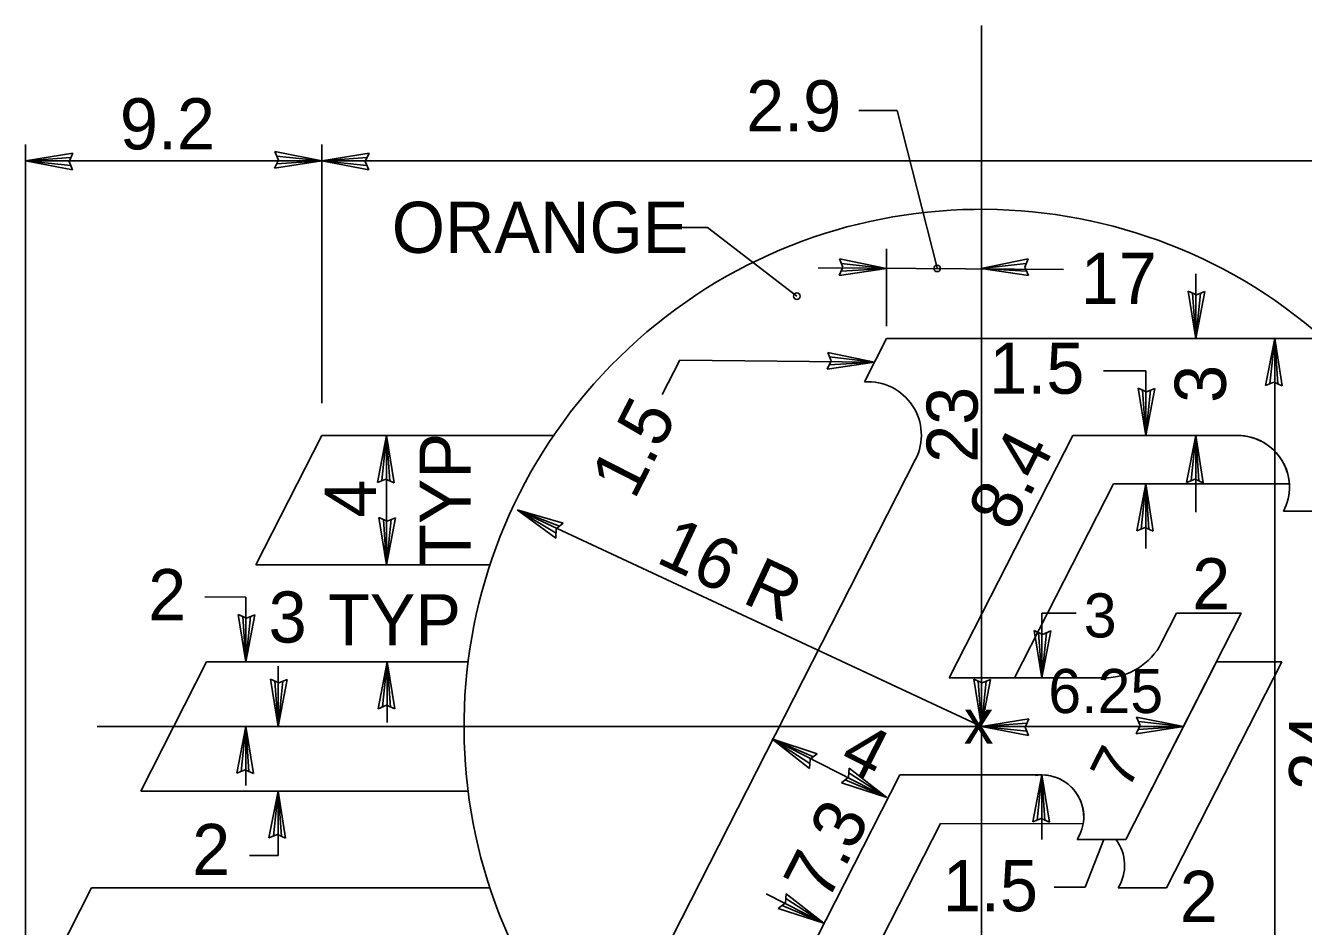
# Model space of a CAD drawing. Extents: x 10268197 to 10269179, y 2141503 to 2142677.
# Drawn here: x 10268467.88 to 10268485.36, y 2142125.76 to 2142138.09 of the extents above; entities that cross this region are included whole.
import ezdxf

# ---------------------------------------------------------------- set-up
doc = ezdxf.new("R2010")
doc.units = 0
for name, color, linetype in [('1', 7, 'Continuous'), ('52', 7, 'Continuous'), ('SOILS_SP83_SHP', 7, 'Continuous')]:
    doc.layers.add(name, color=color, linetype=linetype)

msp = doc.modelspace()

# ---------------------------------------------------------------- linework, layer by layer
at = {"layer": '1'}
for p, q in [((10268480.958, 2142117.747), (10268480.958, 2142138.09)), ((10268479.802, 2142136.926), (10268479.281, 2142136.929)), ((10268479.802, 2142136.926), (10268480.353, 2142134.772)), ((10268467.878, 2142125.164), (10268467.878, 2142136.461)), ((10268471.932, 2142132.921), (10268471.932, 2142136.461)), ((10268467.878, 2142136.24), (10268491.08, 2142136.24)), ((10268476.41, 2142135.328), (10268477.21, 2142135.328)), ((10268477.21, 2142135.328), (10268478.431, 2142134.386)), ((10268479.658, 2142133.976), (10268479.658, 2142135.032)), ((10268482.078, 2142134.75), (10268478.725, 2142134.774)), ((10268483.89, 2142134.691), (10268483.89, 2142133.806)), ((10268484.969, 2142123.188), (10268484.969, 2142133.806)), ((10268476.59, 2142133.039), (10268476.829, 2142133.508)), ((10268476.829, 2142133.508), (10268479.495, 2142133.484)), ((10268483.206, 2142133.364), (10268482.628, 2142133.364)), ((10268483.206, 2142133.364), (10268483.206, 2142132.479)), ((10268472.817, 2142130.709), (10268472.817, 2142132.479)), ((10268480.517, 2142129.161), (10268482.207, 2142132.479)), ((10268482.207, 2142132.479), (10268484.462, 2142132.479)), ((10268483.89, 2142132.479), (10268483.89, 2142131.427)), ((10268482.763, 2142131.815), (10268481.411, 2142129.161)), ((10268485.17, 2142131.815), (10268482.763, 2142131.815)), ((10268483.206, 2142131.815), (10268483.206, 2142130.93)), ((10268480.958, 2142128.497), (10268474.605, 2142131.459)), ((10268470.892, 2142130.267), (10268470.332, 2142130.27)), ((10268470.892, 2142129.382), (10268470.892, 2142130.267)), ((10268481.783, 2142130.046), (10268481.783, 2142129.161)), ((10268481.783, 2142130.046), (10268482.252, 2142130.046)), ((10268471.334, 2142128.497), (10268471.334, 2142129.322)), ((10268472.827, 2142128.552), (10268472.827, 2142129.382)), ((10268482.934, 2142126.949), (10268484.174, 2142129.382)), ((10268485.067, 2142129.382), (10268483.489, 2142126.285)), ((10268484.174, 2142129.382), (10268485.067, 2142129.382)), ((10268481.411, 2142129.161), (10268480.517, 2142129.161)), ((10268468.86, 2142128.497), (10268483.723, 2142128.497)), ((10268470.892, 2142127.689), (10268470.892, 2142128.497)), ((10268479.664, 2142127.521), (10268478.087, 2142128.325)), ((10268478.376, 2142124.957), (10268479.841, 2142127.834)), ((10268479.841, 2142127.834), (10268481.699, 2142127.827)), ((10268481.783, 2142127.834), (10268481.783, 2142126.949)), ((10268471.334, 2142126.727), (10268471.334, 2142127.612)), ((10268480.396, 2142127.168), (10268479.269, 2142124.957)), ((10268482.349, 2142127.162), (10268480.396, 2142127.168)), ((10268482.375, 2142126.297), (10268482.631, 2142126.949)), ((10268482.795, 2142126.949), (10268482.934, 2142126.949)), ((10268471.334, 2142126.727), (10268470.943, 2142126.731)), ((10268478.8, 2142125.802), (10268478.012, 2142126.204)), ((10268481.95, 2142126.297), (10268482.375, 2142126.297)), ((10268483.489, 2142126.285), (10268482.826, 2142126.285))]:
    msp.add_line(p, q, dxfattribs=at)
for centre in [(10268480.35, 2142134.766), (10268478.431, 2142134.385)]:
    msp.add_circle(centre, 0.0442, dxfattribs=at)
for centre, radius, start, end in [((10268484.463, 2142131.77), 0.708, 3.5833, 90), ((10268481.782, 2142127.257), 0.575, 350.3502, 98.3344), ((10268482.341, 2142126.594), 0.575, 327.421, 37.9799)]:
    msp.add_arc(centre, radius, start, end, dxfattribs=at)
at = {"layer": '52'}
for p, q in [((10268467.878, 2142136.24), (10268468.525, 2142136.342)), ((10268468.474, 2142136.229), (10268468.525, 2142136.342)), ((10268471.932, 2142136.24), (10268471.289, 2142136.364)), ((10268471.289, 2142136.364), (10268471.337, 2142136.249)), ((10268471.932, 2142136.24), (10268471.314, 2142136.304)), ((10268471.932, 2142136.24), (10268472.579, 2142136.342)), ((10268472.527, 2142136.229), (10268472.579, 2142136.342)), ((10268467.878, 2142136.24), (10268468.498, 2142136.283)), ((10268467.878, 2142136.24), (10268468.521, 2142136.114)), ((10268467.878, 2142136.24), (10268468.496, 2142136.174)), ((10268468.521, 2142136.114), (10268468.474, 2142136.229)), ((10268471.337, 2142136.249), (10268471.285, 2142136.137)), ((10268471.932, 2142136.24), (10268471.285, 2142136.137)), ((10268471.932, 2142136.24), (10268471.313, 2142136.196)), ((10268471.932, 2142136.24), (10268472.552, 2142136.283)), ((10268471.932, 2142136.24), (10268472.575, 2142136.114)), ((10268471.932, 2142136.24), (10268472.55, 2142136.174)), ((10268472.575, 2142136.114), (10268472.527, 2142136.229)), ((10268479.657, 2142134.765), (10268479.015, 2142134.896)), ((10268479.015, 2142134.896), (10268479.061, 2142134.781)), ((10268480.954, 2142134.765), (10268481.596, 2142134.896)), ((10268481.596, 2142134.896), (10268481.55, 2142134.781)), ((10268479.061, 2142134.781), (10268479.009, 2142134.668)), ((10268479.657, 2142134.765), (10268479.009, 2142134.668)), ((10268479.657, 2142134.765), (10268479.037, 2142134.727)), ((10268479.657, 2142134.765), (10268479.039, 2142134.835)), ((10268480.954, 2142134.765), (10268481.571, 2142134.835)), ((10268480.954, 2142134.765), (10268481.602, 2142134.668)), ((10268480.954, 2142134.765), (10268481.574, 2142134.727)), ((10268481.55, 2142134.781), (10268481.602, 2142134.668)), ((10268483.89, 2142133.806), (10268483.787, 2142134.453)), ((10268483.899, 2142134.402), (10268483.787, 2142134.453)), ((10268483.89, 2142133.806), (10268483.846, 2142134.425)), ((10268483.89, 2142133.806), (10268484.014, 2142134.449)), ((10268483.89, 2142133.806), (10268483.954, 2142134.424)), ((10268484.014, 2142134.449), (10268483.899, 2142134.402)), ((10268484.969, 2142133.806), (10268484.844, 2142133.163)), ((10268484.969, 2142133.806), (10268484.904, 2142133.188)), ((10268484.969, 2142133.806), (10268485.072, 2142133.159)), ((10268484.969, 2142133.806), (10268485.012, 2142133.187)), ((10268478.899, 2142133.5), (10268478.847, 2142133.387)), ((10268479.495, 2142133.484), (10268478.853, 2142133.615)), ((10268478.853, 2142133.615), (10268478.899, 2142133.5)), ((10268479.495, 2142133.484), (10268478.878, 2142133.554)), ((10268479.495, 2142133.484), (10268478.847, 2142133.387)), ((10268479.495, 2142133.484), (10268478.875, 2142133.446)), ((10268484.844, 2142133.163), (10268484.958, 2142133.21)), ((10268484.958, 2142133.21), (10268485.072, 2142133.159)), ((10268483.206, 2142132.479), (10268483.103, 2142133.126)), ((10268483.215, 2142133.074), (10268483.103, 2142133.126)), ((10268483.206, 2142132.479), (10268483.162, 2142133.098)), ((10268483.206, 2142132.479), (10268483.33, 2142133.121)), ((10268483.206, 2142132.479), (10268483.27, 2142133.097)), ((10268483.33, 2142133.121), (10268483.215, 2142133.074)), ((10268472.817, 2142132.479), (10268472.692, 2142131.836)), ((10268472.817, 2142132.479), (10268472.752, 2142131.861)), ((10268472.817, 2142132.479), (10268472.92, 2142131.832)), ((10268472.817, 2142132.479), (10268472.861, 2142131.859)), ((10268483.89, 2142132.479), (10268483.764, 2142131.836)), ((10268483.89, 2142132.479), (10268483.825, 2142131.861)), ((10268483.89, 2142132.479), (10268483.992, 2142131.832)), ((10268483.89, 2142132.479), (10268483.933, 2142131.859)), ((10268472.692, 2142131.836), (10268472.807, 2142131.883)), ((10268472.807, 2142131.883), (10268472.92, 2142131.832)), ((10268483.206, 2142131.815), (10268483.081, 2142131.173)), ((10268483.206, 2142131.815), (10268483.141, 2142131.197)), ((10268483.206, 2142131.815), (10268483.308, 2142131.168)), ((10268483.206, 2142131.815), (10268483.249, 2142131.196)), ((10268483.764, 2142131.836), (10268483.879, 2142131.883)), ((10268483.879, 2142131.883), (10268483.992, 2142131.832)), ((10268474.605, 2142131.459), (10268475.234, 2142131.279)), ((10268474.605, 2142131.459), (10268475.135, 2142131.075)), ((10268474.605, 2142131.459), (10268475.137, 2142131.14)), ((10268474.605, 2142131.459), (10268475.184, 2142131.237)), ((10268472.817, 2142130.709), (10268472.714, 2142131.356)), ((10268472.827, 2142131.305), (10268472.714, 2142131.356)), ((10268472.817, 2142130.709), (10268472.774, 2142131.328)), ((10268472.817, 2142130.709), (10268472.942, 2142131.352)), ((10268472.817, 2142130.709), (10268472.881, 2142131.327)), ((10268472.942, 2142131.352), (10268472.827, 2142131.305)), ((10268475.14, 2142131.199), (10268475.234, 2142131.279)), ((10268483.081, 2142131.173), (10268483.196, 2142131.219)), ((10268483.196, 2142131.219), (10268483.308, 2142131.168)), ((10268475.135, 2142131.075), (10268475.14, 2142131.199)), ((10268470.892, 2142129.382), (10268470.789, 2142130.029)), ((10268470.902, 2142129.977), (10268470.789, 2142130.029)), ((10268470.892, 2142129.382), (10268470.849, 2142130.001)), ((10268470.892, 2142129.382), (10268471.017, 2142130.024)), ((10268470.892, 2142129.382), (10268470.957, 2142130)), ((10268471.017, 2142130.024), (10268470.902, 2142129.977)), ((10268481.783, 2142129.161), (10268481.68, 2142129.808)), ((10268481.793, 2142129.756), (10268481.68, 2142129.808)), ((10268481.783, 2142129.161), (10268481.739, 2142129.78)), ((10268481.783, 2142129.161), (10268481.907, 2142129.803)), ((10268481.783, 2142129.161), (10268481.847, 2142129.779)), ((10268481.907, 2142129.803), (10268481.793, 2142129.756)), ((10268472.827, 2142129.382), (10268472.703, 2142128.739)), ((10268472.827, 2142129.382), (10268472.763, 2142128.764)), ((10268472.827, 2142129.382), (10268472.93, 2142128.735)), ((10268472.827, 2142129.382), (10268472.871, 2142128.762)), ((10268471.334, 2142128.497), (10268471.232, 2142129.144)), ((10268471.344, 2142129.092), (10268471.232, 2142129.144)), ((10268471.334, 2142128.497), (10268471.459, 2142129.14)), ((10268471.459, 2142129.14), (10268471.344, 2142129.092)), ((10268480.958, 2142128.497), (10268480.855, 2142129.144)), ((10268480.968, 2142129.092), (10268480.855, 2142129.144)), ((10268480.958, 2142128.497), (10268481.082, 2142129.14)), ((10268481.082, 2142129.14), (10268480.968, 2142129.092)), ((10268471.334, 2142128.497), (10268471.291, 2142129.116)), ((10268471.334, 2142128.497), (10268471.399, 2142129.115)), ((10268480.958, 2142128.497), (10268480.914, 2142129.116)), ((10268480.958, 2142128.497), (10268481.022, 2142129.115)), ((10268472.703, 2142128.739), (10268472.817, 2142128.786)), ((10268472.817, 2142128.786), (10268472.93, 2142128.735)), ((10268480.958, 2142128.497), (10268481.605, 2142128.599)), ((10268481.553, 2142128.487), (10268481.605, 2142128.599)), ((10268483.723, 2142128.497), (10268483.08, 2142128.622)), ((10268483.08, 2142128.622), (10268483.127, 2142128.507)), ((10268470.892, 2142128.497), (10268470.767, 2142127.854)), ((10268470.892, 2142128.497), (10268470.827, 2142127.879)), ((10268470.892, 2142128.497), (10268470.995, 2142127.85)), ((10268470.892, 2142128.497), (10268470.935, 2142127.877)), ((10268480.958, 2142128.497), (10268481.577, 2142128.54)), ((10268480.958, 2142128.497), (10268481.6, 2142128.372)), ((10268480.958, 2142128.497), (10268481.576, 2142128.432)), ((10268481.6, 2142128.372), (10268481.553, 2142128.487)), ((10268483.127, 2142128.507), (10268483.076, 2142128.394)), ((10268483.723, 2142128.497), (10268483.076, 2142128.394)), ((10268483.723, 2142128.497), (10268483.103, 2142128.453)), ((10268483.723, 2142128.497), (10268483.105, 2142128.562)), ((10268478.087, 2142128.325), (10268478.71, 2142128.123)), ((10268478.087, 2142128.325), (10268478.603, 2142127.922)), ((10268478.087, 2142128.325), (10268478.608, 2142127.987)), ((10268478.087, 2142128.325), (10268478.659, 2142128.082)), ((10268478.613, 2142128.046), (10268478.71, 2142128.123)), ((10268470.767, 2142127.854), (10268470.882, 2142127.901)), ((10268470.882, 2142127.901), (10268470.995, 2142127.85)), ((10268478.603, 2142127.922), (10268478.613, 2142128.046)), ((10268479.148, 2142127.925), (10268479.138, 2142127.801)), ((10268479.664, 2142127.521), (10268479.148, 2142127.925)), ((10268479.138, 2142127.801), (10268479.041, 2142127.723)), ((10268479.664, 2142127.521), (10268479.041, 2142127.723)), ((10268479.664, 2142127.521), (10268479.092, 2142127.764)), ((10268479.664, 2142127.521), (10268479.143, 2142127.86)), ((10268481.783, 2142127.834), (10268481.658, 2142127.191)), ((10268481.783, 2142127.834), (10268481.718, 2142127.215)), ((10268481.783, 2142127.834), (10268481.886, 2142127.186)), ((10268481.783, 2142127.834), (10268481.826, 2142127.214)), ((10268471.334, 2142127.612), (10268471.209, 2142126.969)), ((10268471.334, 2142127.612), (10268471.269, 2142126.994)), ((10268471.334, 2142127.612), (10268471.437, 2142126.965)), ((10268471.334, 2142127.612), (10268471.378, 2142126.993)), ((10268481.658, 2142127.191), (10268481.773, 2142127.237)), ((10268481.773, 2142127.237), (10268481.886, 2142127.186)), ((10268471.209, 2142126.969), (10268471.324, 2142127.016)), ((10268471.324, 2142127.016), (10268471.437, 2142126.965)), ((10268478.284, 2142126.206), (10268478.274, 2142126.082)), ((10268478.8, 2142125.802), (10268478.284, 2142126.206)), ((10268478.274, 2142126.082), (10268478.177, 2142126.005)), ((10268478.8, 2142125.802), (10268478.177, 2142126.005)), ((10268478.8, 2142125.802), (10268478.229, 2142126.045)), ((10268478.8, 2142125.802), (10268478.279, 2142126.14))]:
    msp.add_line(p, q, dxfattribs=at)
at = {"layer": 'SOILS_SP83_SHP'}
for p, q in [((10268479.357, 2142133.212), (10268479.658, 2142133.806)), ((10268479.658, 2142133.806), (10268487.18, 2142133.806)), ((10268471.932, 2142132.479), (10268471.031, 2142130.709)), ((10268471.932, 2142132.479), (10268475.105, 2142132.479)), ((10268482.207, 2142132.479), (10268480.517, 2142129.161)), ((10268480.517, 2142129.161), (10268482.207, 2142132.479)), ((10268484.462, 2142132.479), (10268482.207, 2142132.479)), ((10268482.207, 2142132.479), (10268484.462, 2142132.479)), ((10268476.384, 2142124.946), (10268480.056, 2142132.153)), ((10268482.763, 2142131.815), (10268481.411, 2142129.161)), ((10268485.17, 2142131.815), (10268482.763, 2142131.815)), ((10268485.975, 2142131.441), (10268485.09, 2142131.441)), ((10268471.031, 2142130.709), (10268474.233, 2142130.709)), ((10268484.512, 2142130.046), (10268482.934, 2142126.949)), ((10268483.422, 2142129.644), (10268483.627, 2142130.046)), ((10268483.627, 2142130.046), (10268484.512, 2142130.046)), ((10268470.356, 2142129.382), (10268469.455, 2142127.612)), ((10268470.356, 2142129.382), (10268473.934, 2142129.382)), ((10268482.934, 2142126.949), (10268484.174, 2142129.382)), ((10268485.067, 2142129.382), (10268483.489, 2142126.285)), ((10268484.174, 2142129.382), (10268485.067, 2142129.382)), ((10268480.517, 2142129.161), (10268482.634, 2142129.161)), ((10268481.411, 2142129.161), (10268480.517, 2142129.161)), ((10268479.841, 2142127.834), (10268478.376, 2142124.957)), ((10268478.376, 2142124.957), (10268479.841, 2142127.834)), ((10268481.783, 2142127.834), (10268479.841, 2142127.834)), ((10268479.841, 2142127.834), (10268481.699, 2142127.827)), ((10268469.455, 2142127.612), (10268473.934, 2142127.612)), ((10268480.396, 2142127.168), (10268479.269, 2142124.957)), ((10268482.349, 2142127.162), (10268480.396, 2142127.168)), ((10268482.934, 2142126.949), (10268482.267, 2142126.949)), ((10268482.795, 2142126.949), (10268482.934, 2142126.949)), ((10268468.779, 2142126.285), (10268467.878, 2142124.515)), ((10268468.779, 2142126.285), (10268474.233, 2142126.285)), ((10268483.489, 2142126.285), (10268482.826, 2142126.285))]:
    msp.add_line(p, q, dxfattribs=at)
for centre, radius, start, end in [((10268480.957, 2142128.496), 7.079, 48.5904, 217.4727), ((10268479.405, 2142132.484), 0.73, 332.9998, 93.8045), ((10268484.463, 2142131.77), 0.708, 332.2089, 90), ((10268484.463, 2142131.77), 0.708, 3.5833, 90), ((10268482.634, 2142130.045), 0.885, 270, 332.9883), ((10268481.782, 2142127.257), 0.575, 350.3502, 98.3344), ((10268481.782, 2142127.257), 0.575, 327.421, 90), ((10268482.341, 2142126.594), 0.575, 327.421, 37.9799)]:
    msp.add_arc(centre, radius, start, end, dxfattribs=at)

# ---------------------------------------------------------------- texts
at = {"layer": '1'}
for s, height, p in [('2.9', 0.7, (10268477.737, 2142136.641)), ('9.2', 0.7, (10268469.169, 2142136.395)), ('ORANGE', 0.7, (10268472.889, 2142134.978)), ('17', 0.7, (10268482.314, 2142134.279)), ('1.5', 0.7, (10268481.064, 2142133.05)), ('2', 0.7, (10268483.84, 2142130.099)), ('2', 0.7, (10268469.556, 2142129.95)), ('3', 0.7, (10268471.204, 2142129.644)), ('TYP', 0.7, (10268472.016, 2142129.606)), ('3', 0.604, (10268482.357, 2142129.714)), ('6.25', 0.6037, (10268481.872, 2142128.679)), ('x', 0.604, (10268480.717, 2142128.261)), ('2', 0.7, (10268470.158, 2142126.462)), ('1.5', 0.7, (10268480.429, 2142125.966)), ('2', 0.7, (10268483.67, 2142125.82))]:
    msp.add_text(s, height=height, dxfattribs=at).set_placement(p)
for s, height, rotation, p in [('3', 0.7, 90, (10268484.301, 2142132.925)), ('1.5', 0.7, 63, (10268476.208, 2142131.585)), ('23', 0.7, 90, (10268480.906, 2142132.104)), ('TYP', 0.7, 90, (10268473.969, 2142130.693)), ('8.4', 0.7, 63, (10268481.367, 2142131.141)), ('4', 0.7, 90, (10268472.672, 2142131.354)), ('16 R', 0.7, 334.9991, (10268476.485, 2142130.75)), ('24', 0.7, 90, (10268485.866, 2142127.625)), ('4', 0.7, 332.9866, (10268478.984, 2142127.964)), ('7', 0.604, 63, (10268482.958, 2142127.606)), ('7.3', 0.7, 63, (10268478.847, 2142126.078))]:
    msp.add_text(s, height=height, rotation=rotation, dxfattribs=at).set_placement(p)

doc.saveas('drawing.dxf')
